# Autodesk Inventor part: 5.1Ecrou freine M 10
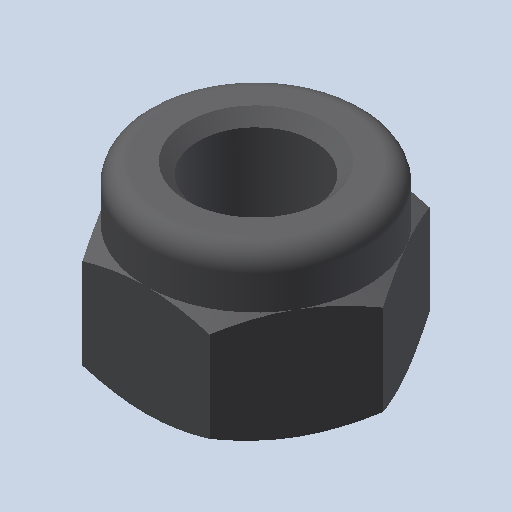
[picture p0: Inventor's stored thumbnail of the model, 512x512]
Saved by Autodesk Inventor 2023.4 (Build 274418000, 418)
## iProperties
Created: 2011-01
Part Number: 5.1Ecrou freine M 10
Document SubType Name: Modeling
Designer: eric
Density: 1 g/cm^3
Mass: 1.8546 g
Surface Area: 12.1018 cm^2
Volume: 1.8546 cm^3
Material: Générique
Appearance: Red
Author: eric
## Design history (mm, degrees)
feature "Base1"
node "Corps solides"
node "Corps surfaciques"
node "Solide1"
